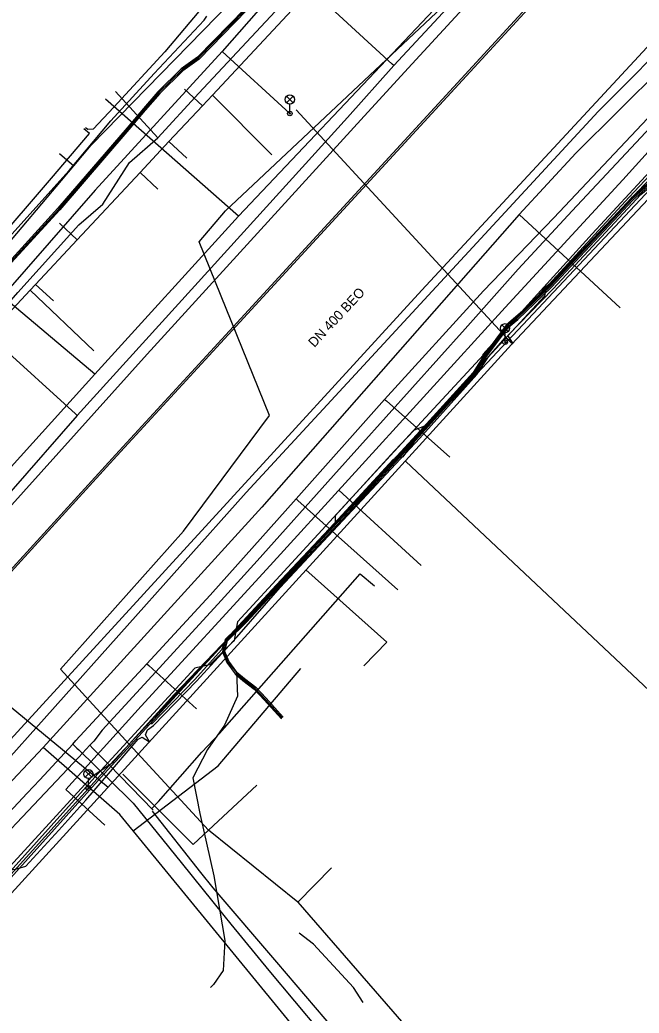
# Model space of a CAD drawing. Extents: x -598932 to -598196, y -1162210 to -1161504.
# Drawn here: x -598439.1 to -598388.2, y -1161629.7 to -1161548 of the extents above; entities that cross this region are included whole.
import ezdxf

# ---------------------------------------------------------------- set-up
doc = ezdxf.new("R2010")
doc.units = 0
for name, color, linetype in [('Vrstva 1', 7, 'Continuous'), ('Vrstva 12', 7, 'Continuous'), ('Vrstva 13', 7, 'Continuous'), ('Vrstva 14', 7, 'Continuous'), ('Vrstva 16', 7, 'Continuous'), ('Vrstva 25', 7, 'Continuous'), ('Vrstva 33', 7, 'Continuous'), ('Vrstva 4', 7, 'Continuous'), ('Vrstva 42', 7, 'Continuous'), ('Vrstva 44', 7, 'Continuous'), ('Vrstva 52', 7, 'Continuous'), ('Vrstva 53', 7, 'Continuous'), ('Vrstva 54', 7, 'Continuous'), ('Vrstva 55', 7, 'Continuous'), ('Vrstva 58', 7, 'Continuous'), ('Vrstva 9', 7, 'Continuous')]:
    doc.layers.add(name, color=color, linetype=linetype)

msp = doc.modelspace()

# ---------------------------------------------------------------- linework, layer by layer
at = {"layer": 'Vrstva 1'}
for p, q in [((-598418.395, -1161559.1), (-598423.28, -1161554.174)), ((-598433.038, -1161575.208), (-598438.276, -1161570.23)), ((-598414.969, -1161624.057), (-598416.142, -1161623.14)), ((-598413.322, -1161625.84), (-598414.969, -1161624.057)), ((-598411.677, -1161627.622), (-598413.322, -1161625.84)), ((-598410.884, -1161628.842), (-598411.677, -1161627.622))]:
    msp.add_line(p, q, dxfattribs=at)
msp.add_lwpolyline([(-598343.372, -1161505.182), (-598349.192, -1161510.657), (-598372.233, -1161533.783), (-598382.612, -1161544.945), (-598406.057, -1161570.232), (-598441.133, -1161608.511), (-598461.94, -1161630.69)], dxfattribs=at)
at = {"layer": 'Vrstva 12'}
for p, q in [((-598435.85, -1161558.98), (-598434.69, -1161560.01)), ((-598435.7, -1161561.21), (-598434.69, -1161560.01)), ((-598440.54, -1161566.96), (-598435.7, -1161561.21)), ((-598430.12, -1161607.59), (-598431.53, -1161609.16))]:
    msp.add_line(p, q, dxfattribs=at)
for points in [[(-598434.69, -1161560.01), (-598433.26, -1161558.3), (-598419.49, -1161544.16)], [(-598376.1, -1161548.28), (-598386.97, -1161560.12), (-598392.04, -1161565.6), (-598401.02, -1161575.53), (-598400.96, -1161576.11), (-598405.82, -1161581.42), (-598406.68, -1161581.75), (-598408.29, -1161583.46)], [(-598408.29, -1161583.46), (-598413.18, -1161588.8), (-598413.19, -1161589.38), (-598416.15, -1161592.75)], [(-598416.15, -1161592.75), (-598416.87, -1161593.55), (-598417.86, -1161594.58)], [(-598417.86, -1161594.58), (-598426.46, -1161603.54), (-598430.12, -1161607.59)], [(-598431.53, -1161609.16), (-598433.21, -1161610.29), (-598433.77, -1161610.9)], [(-598433.77, -1161610.9), (-598466.88, -1161647.08), (-598467.08, -1161647.64), (-598467.77, -1161648.05), (-598484.01, -1161665.77)]]:
    msp.add_lwpolyline(points, dxfattribs=at)
at = {"layer": 'Vrstva 13'}
for p, q in [((-598423.61, -1161614.68), (-598430.12, -1161607.59)), ((-598423.61, -1161614.68), (-598419.63, -1161610.96)), ((-598416.26, -1161620.6), (-598423.61, -1161614.68)), ((-598416.26, -1161620.6), (-598413.48, -1161617.78))]:
    msp.add_line(p, q, dxfattribs=at)
for points in [[(-598430.12, -1161607.59), (-598435.78, -1161601.42), (-598425.66, -1161590.05), (-598418.57, -1161580.53), (-598424.37, -1161566.24), (-598422.21, -1161563.71), (-598395.3, -1161538.39)], [(-598375.53, -1161609.75), (-598377.98, -1161611.98), (-598407.406, -1161584.292)], [(-598415.599, -1161593.241), (-598408.92, -1161599.19), (-598410.82, -1161601.15)], [(-598430.649, -1161610.045), (-598424.86, -1161615.86), (-598423.61, -1161614.68)], [(-598416.26, -1161620.6), (-598377.36, -1161665.37), (-598350.98, -1161698.49), (-598350.65, -1161701.02), (-598363.75, -1161706.8)]]:
    msp.add_lwpolyline(points, dxfattribs=at)
at = {"layer": 'Vrstva 14'}
for p, q in [((-598437.483, -1161610.512), (-598434.77, -1161607.58)), ((-598434.77, -1161607.58), (-598434.51, -1161607.3)), ((-598434.77, -1161607.58), (-598434.44, -1161607.92))]:
    msp.add_line(p, q, dxfattribs=at)
for points in [[(-598597.949, -1161786.696), (-598594.355, -1161782.22), (-598591.124, -1161778.235), (-598590.488, -1161777.45), (-598568.259, -1161750.324), (-598540.145, -1161717.756), (-598494.895, -1161668.814), (-598474.946, -1161646.048), (-598446.726, -1161616.22), (-598420.512, -1161586.879), (-598391.532, -1161555.529), (-598341.416, -1161505.182)], [(-598434.51, -1161607.3), (-598428.667, -1161600.975), (-598423.458, -1161595.34), (-598416.396, -1161587.407), (-598409.107, -1161579.217), (-598400.965, -1161570.28), (-598395.18, -1161564.29), (-598384.777, -1161553.222), (-598372.381, -1161540.174), (-598369.354, -1161537.052), (-598360.828, -1161528.274), (-598349.918, -1161517.368), (-598344.393, -1161512.034), (-598337.213, -1161505.182)], [(-598361.731, -1161505.182), (-598365.2, -1161508.354), (-598377.411, -1161519.954), (-598395.234, -1161538.978), (-598407.179, -1161551.973), (-598411.055, -1161556.218), (-598428.638, -1161575.491)], [(-598378.256, -1161519.804), (-598395.164, -1161537.544), (-598408.344, -1161551.754), (-598412.164, -1161556.015), (-598420.701, -1161565.422), (-598434.416, -1161580.555), (-598439.854, -1161586.796), (-598439.977, -1161586.934), (-598440.475, -1161587.492), (-598446.946, -1161594.711), (-598449.055, -1161597.092)], [(-598408.344, -1161551.754), (-598408.491, -1161551.62), (-598420.221, -1161540.827)], [(-598434.416, -1161580.555), (-598434.556, -1161580.418), (-598447.351, -1161568.768)], [(-598573.404, -1161732.925), (-598571.604, -1161731.052), (-598554.514, -1161713.376), (-598533.774, -1161691.098), (-598513.523, -1161668.723), (-598504.735, -1161659.069), (-598494, -1161647.223), (-598480.574, -1161632.154), (-598477.858, -1161629.221), (-598469.826, -1161620.401), (-598456.055, -1161605.679), (-598446.117, -1161594.93), (-598428.638, -1161575.491)], [(-598409.107, -1161579.217), (-598408.953, -1161579.349), (-598403.74, -1161583.985)], [(-598416.396, -1161587.407), (-598416.247, -1161587.539), (-598408.027, -1161594.897)], [(-598428.667, -1161600.975), (-598428.516, -1161601.104), (-598424.588, -1161604.695)], [(-598434.44, -1161607.92), (-598434.28, -1161608.06), (-598430.118, -1161612.12), (-598429.79, -1161612.44), (-598425.84, -1161617.34), (-598422.35, -1161621.7), (-598421.77, -1161622.39), (-598418.63, -1161626.21), (-598414.403, -1161631.27), (-598411.04, -1161635.5), (-598407.33, -1161639.96), (-598403.47, -1161644.54), (-598399.66, -1161649.12), (-598395.46, -1161654.09), (-598391.97, -1161658.25), (-598388.12, -1161662.68), (-598384.09, -1161667.15), (-598380.912, -1161670.581), (-598380.07, -1161671.49), (-598379.76, -1161671.83), (-598379.5, -1161672.11), (-598379.3, -1161672.33)], [(-598589.947, -1161792.741), (-598577.445, -1161777.792), (-598565.596, -1161764.237), (-598559.546, -1161757.337), (-598558.635, -1161756.275), (-598558.918, -1161751.624), (-598555.314, -1161747.837), (-598550.53, -1161742.727), (-598537.985, -1161729.402), (-598525.355, -1161715.849), (-598512.719, -1161702.199), (-598500.184, -1161688.704), (-598495.944, -1161684.141), (-598496.644, -1161675.242), (-598493.647, -1161671.551), (-598491.273, -1161668.615), (-598474.912, -1161650.419), (-598466.442, -1161641.794), (-598445.99, -1161619.606), (-598438.518, -1161611.629), (-598437.483, -1161610.512)]]:
    msp.add_lwpolyline(points, dxfattribs=at)
at = {"layer": 'Vrstva 16'}
for p, q in [((-598421.13, -1161564.15), (-598432.09, -1161554.52)), ((-598432.96, -1161577.15), (-598443.51, -1161568.25))]:
    msp.add_line(p, q, dxfattribs=at)
for points in [[(-598473.2, -1161621.09), (-598461.78, -1161608.24), (-598461.37, -1161607.74), (-598455.64, -1161601.25), (-598454.96, -1161600.54), (-598448.54, -1161593.94), (-598441.66, -1161586.74), (-598432.96, -1161577.15), (-598421.13, -1161564.15), (-598392.87, -1161534.27), (-598377.76, -1161518.29), (-598376.98, -1161517.48), (-598363.01, -1161531.33), (-598362.8, -1161531.54)], [(-598386.81, -1161556.37), (-598393.69, -1161563.71), (-598398.11, -1161568.49), (-598402.48, -1161573.4), (-598413.33, -1161585.48), (-598419.6, -1161592.5), (-598422.55, -1161595.77), (-598427.36, -1161601.01), (-598427.63, -1161601.31), (-598432.34, -1161606.44), (-598433.05, -1161607.34), (-598433.36, -1161607.68), (-598434.26, -1161608.65), (-598444.97, -1161619.96), (-598446.86, -1161621.99), (-598450.89, -1161626.24), (-598466.05, -1161642.27)], [(-598428.3, -1161612.9), (-598427.72, -1161612.32), (-598424.15, -1161608.25), (-598422.7, -1161606.71), (-598411.12, -1161593.58), (-598409.93, -1161594.57)], [(-598433.36, -1161607.68), (-598433.11, -1161607.94), (-598432.87, -1161608.18)], [(-598432.87, -1161608.18), (-598431.79, -1161609.27), (-598428.15, -1161613.03)], [(-598428.24, -1161613.09), (-598424.26, -1161618.14), (-598423.24, -1161619.42), (-598418.02, -1161625.54), (-598412.43, -1161632.07), (-598404.72, -1161641.34), (-598397.7, -1161649.87), (-598389.4, -1161659.98), (-598381.32, -1161668.94), (-598373.27, -1161677.49), (-598372.93, -1161677.81)]]:
    msp.add_lwpolyline(points, dxfattribs=at)
at = {"layer": 'Vrstva 25'}
msp.add_line((-598406.108, -1161592.876), (-598412.865, -1161586.69), dxfattribs=at)
msp.add_lwpolyline([(-598337.905, -1161512.847), (-598343.578, -1161518.811), (-598343.765, -1161519.003), (-598344.954, -1161520.122), (-598347.721, -1161517.478), (-598359.628, -1161529.548), (-598369.265, -1161539.404), (-598381.967, -1161552.798), (-598389.513, -1161561.16), (-598399.193, -1161571.667), (-598418.515, -1161592.898), (-598429.145, -1161604.475), (-598435.329, -1161611.328), (-598432.136, -1161614.261)], dxfattribs=at)
at = {"layer": 'Vrstva 33'}
for p, q in [((-598417.175, -1161554.275), (-598416.645, -1161554.805)), ((-598417.175, -1161554.805), (-598416.645, -1161554.275)), ((-598416.91, -1161555.69), (-598416.91, -1161554.915)), ((-598399.462, -1161573.095), (-598398.932, -1161573.625)), ((-598399.462, -1161573.625), (-598398.932, -1161573.095)), ((-598399.197, -1161574.51), (-598399.197, -1161573.735)), ((-598433.745, -1161609.785), (-598433.215, -1161610.315)), ((-598433.745, -1161610.315), (-598433.215, -1161609.785)), ((-598433.48, -1161611.2), (-598433.48, -1161610.425))]:
    msp.add_line(p, q, dxfattribs=at)
for centre, radius in [((-598416.91, -1161554.54), 0.375), ((-598416.91, -1161555.69), 0.19), ((-598416.91, -1161555.69), 0.05), ((-598399.197, -1161573.36), 0.375), ((-598399.197, -1161574.51), 0.19), ((-598399.197, -1161574.51), 0.05), ((-598433.48, -1161610.05), 0.375), ((-598433.48, -1161611.2), 0.19), ((-598433.48, -1161611.2), 0.05)]:
    msp.add_circle(centre, radius, dxfattribs=at)
at = {"layer": 'Vrstva 42'}
for points in [[(-598514.881, -1161675.495), (-598514.586, -1161675.706), (-598514.544, -1161675.66), (-598509.789, -1161670.451), (-598509.79, -1161670.452), (-598495.271, -1161654.682), (-598493.794, -1161653.11), (-598482.467, -1161640.638), (-598481.951, -1161640.136), (-598458.21, -1161613.742), (-598445.27, -1161599.978), (-598445.069, -1161599.756), (-598441.565, -1161595.287), (-598431.149, -1161583.871), (-598378.675, -1161526.796), (-598362.821, -1161511.358), (-598362.827, -1161511.253), (-598362.686, -1161511.241), (-598356.249, -1161505.182)], [(-598514.881, -1161675.495), (-598514.586, -1161675.706), (-598514.544, -1161675.66), (-598509.789, -1161670.451), (-598509.79, -1161670.452), (-598495.271, -1161654.682), (-598493.794, -1161653.11), (-598482.467, -1161640.638), (-598481.951, -1161640.136), (-598458.21, -1161613.742), (-598445.27, -1161599.978), (-598445.069, -1161599.756), (-598441.565, -1161595.287), (-598431.149, -1161583.871), (-598378.675, -1161526.796), (-598362.821, -1161511.358), (-598362.827, -1161511.253), (-598362.686, -1161511.241), (-598356.249, -1161505.182)], [(-598482.615, -1161640.14), (-598481.951, -1161640.136), (-598458.21, -1161613.742), (-598445.27, -1161599.978), (-598445.069, -1161599.756), (-598441.565, -1161595.287), (-598431.149, -1161583.871), (-598378.675, -1161526.796), (-598362.821, -1161511.358), (-598362.827, -1161511.253), (-598362.686, -1161511.241), (-598356.249, -1161505.182)], [(-598445.533, -1161599.605), (-598445.069, -1161599.756), (-598441.565, -1161595.287), (-598431.149, -1161583.871), (-598378.675, -1161526.796), (-598362.821, -1161511.358), (-598362.827, -1161511.253), (-598362.686, -1161511.241), (-598356.249, -1161505.182)], [(-598333.292, -1161506.719), (-598333.648, -1161506.343), (-598340.064, -1161512.561), (-598347.279, -1161519.411), (-598358.645, -1161530.791), (-598359.016, -1161531.162), (-598364.326, -1161536.555), (-598366.568, -1161538.905), (-598386.088, -1161559.982), (-598386.486, -1161560.187), (-598387.137, -1161560.908), (-598388.837, -1161562.698), (-598395.469, -1161569.9), (-598395.861, -1161570.273), (-598395.968, -1161570.71), (-598399.644, -1161574.699), (-598405.348, -1161580.864), (-598405.5, -1161581.11), (-598406.04, -1161581.87)], [(-598378.78, -1161526.689), (-598382.177, -1161530.367), (-598431.26, -1161583.77)], [(-598424.39, -1161547.288), (-598427.2, -1161550.618), (-598431.4, -1161555.158), (-598433.09, -1161556.988), (-598433.54, -1161557.018), (-598433.73, -1161556.868)], [(-598476.465, -1161608.22), (-598472.955, -1161603.94), (-598470.26, -1161600.54), (-598467.44, -1161597.3), (-598464.29, -1161594.03), (-598463.6, -1161593.88), (-598462.87, -1161593), (-598462.63, -1161592.07), (-598462.06, -1161590.94), (-598457.31, -1161585.43), (-598452.529, -1161580.011), (-598447.689, -1161574.381), (-598444.21, -1161570.46), (-598441.3, -1161567.26), (-598435.08, -1161560.38), (-598431.65, -1161556.3), (-598428.06, -1161552.41), (-598423.96, -1161548), (-598423.74, -1161547.69)], [(-598445.688, -1161570.879), (-598445.492, -1161571.041), (-598445.34, -1161571.11), (-598445.09, -1161571.04), (-598441.5, -1161566.79), (-598436.51, -1161561.02), (-598433.4, -1161557.329), (-598433.849, -1161556.964)], [(-598387.283, -1161560.772), (-598388.983, -1161562.562), (-598395.611, -1161569.76), (-598395.999, -1161570.127), (-598396.197, -1161570.368), (-598399.938, -1161574.427), (-598406.758, -1161581.798), (-598417.087, -1161593.013), (-598421.217, -1161597.515), (-598421.344, -1161598.244), (-598421.49, -1161599.08), (-598421.65, -1161599.23), (-598422.7, -1161600.27), (-598423.08, -1161600.65), (-598423.5, -1161601.06), (-598424.039, -1161601.179), (-598424.72, -1161601.33), (-598432.474, -1161609.755), (-598445.008, -1161623.694), (-598461.236, -1161641.709)], [(-598406.04, -1161581.87), (-598407.62, -1161583.94), (-598408.397, -1161584.168), (-598416.793, -1161593.283), (-598421.344, -1161598.244), (-598423.305, -1161600.382), (-598424.039, -1161601.179), (-598432.178, -1161610.025), (-598444.71, -1161623.962), (-598460.94, -1161641.979), (-598483.892, -1161666.804), (-598490.009, -1161673.693), (-598489.744, -1161674.222), (-598490.288, -1161673.987), (-598492.973, -1161677.375), (-598495.513, -1161681.565), (-598498.183, -1161687.257), (-598495.776, -1161690.441)], [(-598431.26, -1161583.77), (-598441.68, -1161595.19), (-598444.698, -1161599.071), (-598445.156, -1161599.624), (-598445.433, -1161599.698)]]:
    msp.add_lwpolyline(points, dxfattribs=at)
at = {"layer": 'Vrstva 44'}
for points in [[(-598420.593, -1161547.051), (-598424.505, -1161551.064), (-598425.845, -1161552.023), (-598427.763, -1161553.902), (-598428.956, -1161555.285), (-598430.306, -1161556.875), (-598435.995, -1161563.494), (-598440.894, -1161568.843)], [(-598420.447, -1161547.189), (-598424.375, -1161551.216), (-598425.716, -1161552.177), (-598427.617, -1161554.038), (-598428.804, -1161555.415), (-598430.154, -1161557.005), (-598435.845, -1161563.626), (-598440.745, -1161568.977)], [(-598386.895, -1161560.974), (-598388.83, -1161562.668), (-598395.521, -1161569.84), (-598398.297, -1161572.496), (-598399.053, -1161573.141), (-598400.853, -1161575.543), (-598401.78, -1161577.029), (-598406.444, -1161582.153), (-598407.394, -1161583.192), (-598411.013, -1161587.121), (-598412.323, -1161588.491), (-598413.583, -1161589.832), (-598417.943, -1161594.512), (-598420.592, -1161597.39), (-598422.221, -1161598.989), (-598422.455, -1161599.978), (-598422.097, -1161600.871), (-598421.401, -1161601.811)], [(-598421.259, -1161601.669), (-598421.923, -1161600.769), (-598422.245, -1161599.962), (-598422.039, -1161599.091), (-598420.448, -1161597.53), (-598417.797, -1161594.648), (-598413.437, -1161589.968), (-598412.177, -1161588.629), (-598410.867, -1161587.258), (-598407.246, -1161583.328), (-598406.296, -1161582.287), (-598401.62, -1161577.151), (-598400.688, -1161575.657), (-598398.907, -1161573.279), (-598398.163, -1161572.644), (-598395.379, -1161569.98), (-598388.69, -1161562.812), (-598386.765, -1161561.126)], [(-598421.401, -1161601.811), (-598420.773, -1161602.348), (-598419.847, -1161603.054), (-598419.013, -1161603.948), (-598417.604, -1161605.497)], [(-598421.259, -1161601.669), (-598420.647, -1161602.192), (-598419.713, -1161602.906), (-598418.866, -1161603.812), (-598417.456, -1161605.363)]]:
    msp.add_lwpolyline(points, dxfattribs=at)
at = {"layer": 'Vrstva 52'}
msp.add_lwpolyline([(-598382.98, -1161519.06), (-598365.39, -1161539.3), (-598398.68, -1161574.69), (-598431.92, -1161611.17), (-598468.58, -1161651.39), (-598447.43, -1161669.94)], dxfattribs=at)
at = {"layer": 'Vrstva 53'}
for points in [[(-598420.52, -1161547.12), (-598424.44, -1161551.14), (-598425.78, -1161552.1), (-598427.69, -1161553.97), (-598428.88, -1161555.35), (-598430.23, -1161556.94), (-598435.92, -1161563.56), (-598440.82, -1161568.91), (-598442.02, -1161570.28), (-598443.72, -1161572.07), (-598447, -1161575.75), (-598447.74, -1161576.01), (-598448.7, -1161576), (-598451.71, -1161574.47), (-598453.62, -1161573.44), (-598455.23, -1161572.23), (-598457.14, -1161570.6), (-598458.86, -1161569.12), (-598462.13, -1161566.37), (-598465.3, -1161563.52), (-598467.49, -1161561.86)], [(-598374.06, -1161549.5), (-598374.78, -1161548.77), (-598374.96, -1161548.71), (-598375.26, -1161548.8), (-598381.58, -1161555.56), (-598385.47, -1161559.76), (-598387.18, -1161561.26), (-598388.34, -1161562.16), (-598395.59, -1161569.83), (-598397.75, -1161571.92), (-598399.1, -1161573.11), (-598400.88, -1161575.52), (-598401.82, -1161577.01), (-598406.5, -1161582.14), (-598411.05, -1161587.08), (-598418.03, -1161594.5), (-598422.17, -1161598.99), (-598422.54, -1161599.82), (-598424.73, -1161602.28), (-598428.29, -1161605.95)]]:
    msp.add_lwpolyline(points, dxfattribs=at)
at = {"layer": 'Vrstva 54'}
for p, q in [((-598398.682, -1161574.601), (-598416.376, -1161555.389)), ((-598452.066, -1161594.557), (-598431.867, -1161611.127))]:
    msp.add_line(p, q, dxfattribs=at)
at = {"layer": 'Vrstva 55'}
for points in [[(-598593.724, -1161815.599), (-598601.79, -1161825.2), (-598612.66, -1161816.58), (-598605.21, -1161808.89), (-598597.75, -1161800.73), (-598596.12, -1161801.43), (-598593.55, -1161803.29), (-598583.76, -1161792.8), (-598587.73, -1161788.84), (-598556.49, -1161751.54), (-598543.66, -1161733.82), (-598504.5, -1161691.15), (-598500.07, -1161684.86), (-598483.28, -1161665.74), (-598469.525, -1161651.138), (-598469.135, -1161651.28), (-598469.525, -1161651.138), (-598431.76, -1161609.32), (-598365.821, -1161539.037), (-598342.93, -1161515.615), (-598331.661, -1161505.182)], [(-598402.127, -1161505.182), (-598389.64, -1161508.67), (-598391.671, -1161515.864), (-598383.066, -1161519.277), (-598391.671, -1161515.864), (-598393.76, -1161520.96), (-598414.51, -1161541.48), (-598422.48, -1161550.58), (-598416.91, -1161555.69), (-598422.48, -1161550.58), (-598432.92, -1161562), (-598457.17, -1161589.74), (-598451.81, -1161594.17), (-598457.4, -1161589.74), (-598474.66, -1161610.02)], [(-598398.52, -1161574.61), (-598398.98, -1161573.95), (-598395.23, -1161570.13), (-598388.03, -1161562.36), (-598386.67, -1161561.24), (-598385.21, -1161559.99), (-598381.27, -1161555.7), (-598374.75, -1161548.74), (-598368.98, -1161542.67), (-598367.41, -1161540.81), (-598366.86, -1161539.93), (-598366.63, -1161539.32), (-598366.07, -1161538.76), (-598365.32, -1161539.19)], [(-598428.14, -1161606.05), (-598424.6, -1161602.41), (-598421.27, -1161598.79), (-598417.7, -1161594.71), (-598406.21, -1161582.4), (-598401.52, -1161577.18), (-598400.56, -1161575.71), (-598399.17, -1161574.13), (-598398.52, -1161574.61)], [(-598428.45, -1161607.4), (-598428.78, -1161606.83), (-598428.62, -1161606.42), (-598428.14, -1161606.05)], [(-598468.56, -1161651.3), (-598468.8, -1161650.92), (-598468.2, -1161650.22), (-598462, -1161643.38), (-598455.58, -1161636.34), (-598449.33, -1161629.52), (-598444.94, -1161624.6), (-598440.7, -1161619.91), (-598440.57, -1161619.18), (-598440.56, -1161618.45), (-598440.13, -1161617.97), (-598439.49, -1161617.87), (-598438.64, -1161617.64), (-598435.93, -1161614.67), (-598433.69, -1161612.19), (-598432.15, -1161610.42), (-598429.39, -1161607.17), (-598429.06, -1161607.01), (-598428.45, -1161607.4)]]:
    msp.add_lwpolyline(points, dxfattribs=at)
at = {"layer": 'Vrstva 58'}
msp.add_line((-598427.76, -1161557.7), (-598431.25, -1161553.89), dxfattribs=at)
for points in [[(-598427.76, -1161557.7), (-598424.4, -1161554.02), (-598418.12, -1161547.31), (-598417.03, -1161545.9), (-598413.89, -1161542.64), (-598406.07, -1161535.43)], [(-598441.73, -1161573.18), (-598439.28, -1161570.43), (-598434.27, -1161564.84), (-598432.3, -1161563.14), (-598430.11, -1161559.72), (-598427.76, -1161557.7)], [(-598386.83, -1161561.05), (-598388.76, -1161562.74), (-598395.45, -1161569.91), (-598398.23, -1161572.57), (-598398.98, -1161573.21), (-598400.77, -1161575.6), (-598401.7, -1161577.09), (-598406.37, -1161582.22), (-598410.94, -1161587.19), (-598413.51, -1161589.9), (-598417.87, -1161594.58), (-598420.52, -1161597.46), (-598422.13, -1161599.04), (-598422.35, -1161599.97), (-598422.01, -1161600.82), (-598421.3, -1161601.7), (-598421.22, -1161603.65), (-598422.28, -1161606.02), (-598423.68, -1161608.04), (-598424.9, -1161610.37), (-598424.32, -1161613.29), (-598423.16, -1161618.43), (-598422.27, -1161623.74), (-598422.4, -1161626.22), (-598423.2, -1161627.36), (-598423.45, -1161627.62)], [(-598421.33, -1161601.74), (-598420.71, -1161602.27), (-598419.78, -1161602.98), (-598418.94, -1161603.88), (-598417.53, -1161605.43)]]:
    msp.add_lwpolyline(points, dxfattribs=at)
at = {"layer": 'Vrstva 9'}
for p, q in [((-598359.28, -1161525.04), (-598393.38, -1161558.95)), ((-598425.567, -1161553.693), (-598424.106, -1161555.058)), ((-598425.394, -1161559.369), (-598426.856, -1161558.004)), ((-598427.77, -1161561.912), (-598429.232, -1161560.547)), ((-598435.868, -1161564.721), (-598434.406, -1161566.086)), ((-598389.732, -1161571.673), (-598398.05, -1161564.003)), ((-598436.37, -1161571.12), (-598437.832, -1161569.755)), ((-598419.211, -1161588.094), (-598437.199, -1161607.856)), ((-598422.818, -1161609.362), (-598416.002, -1161601.373)), ((-598437.199, -1161607.856), (-598445.884, -1161617.098)), ((-598430.894, -1161613.37), (-598437.199, -1161607.856)), ((-598429.791, -1161614.717), (-598422.818, -1161609.362)), ((-598409.077, -1161640.014), (-598430.894, -1161613.37))]:
    msp.add_line(p, q, dxfattribs=at)
for points in [[(-598412.76, -1161542.91), (-598414.031, -1161544.271), (-598415.581, -1161545.93), (-598423.28, -1161554.174), (-598424.106, -1161555.058), (-598426.856, -1161558.003), (-598429.232, -1161560.547), (-598434.406, -1161566.086), (-598437.832, -1161569.755), (-598438.276, -1161570.23), (-598444.399, -1161576.785), (-598446.494, -1161579.029), (-598447.306, -1161579.899), (-598451.9, -1161584.818), (-598453.06, -1161586.06)], [(-598393.38, -1161558.95), (-598398.05, -1161564.003), (-598419.211, -1161588.094)]]:
    msp.add_lwpolyline(points, dxfattribs=at)

# ---------------------------------------------------------------- texts
at = {"layer": 'Vrstva 4'}
msp.add_text('DN 400 BEO', height=0.8, rotation=47, dxfattribs=at).set_placement((-598414.89, -1161574.991))

doc.saveas('drawing.dxf')
